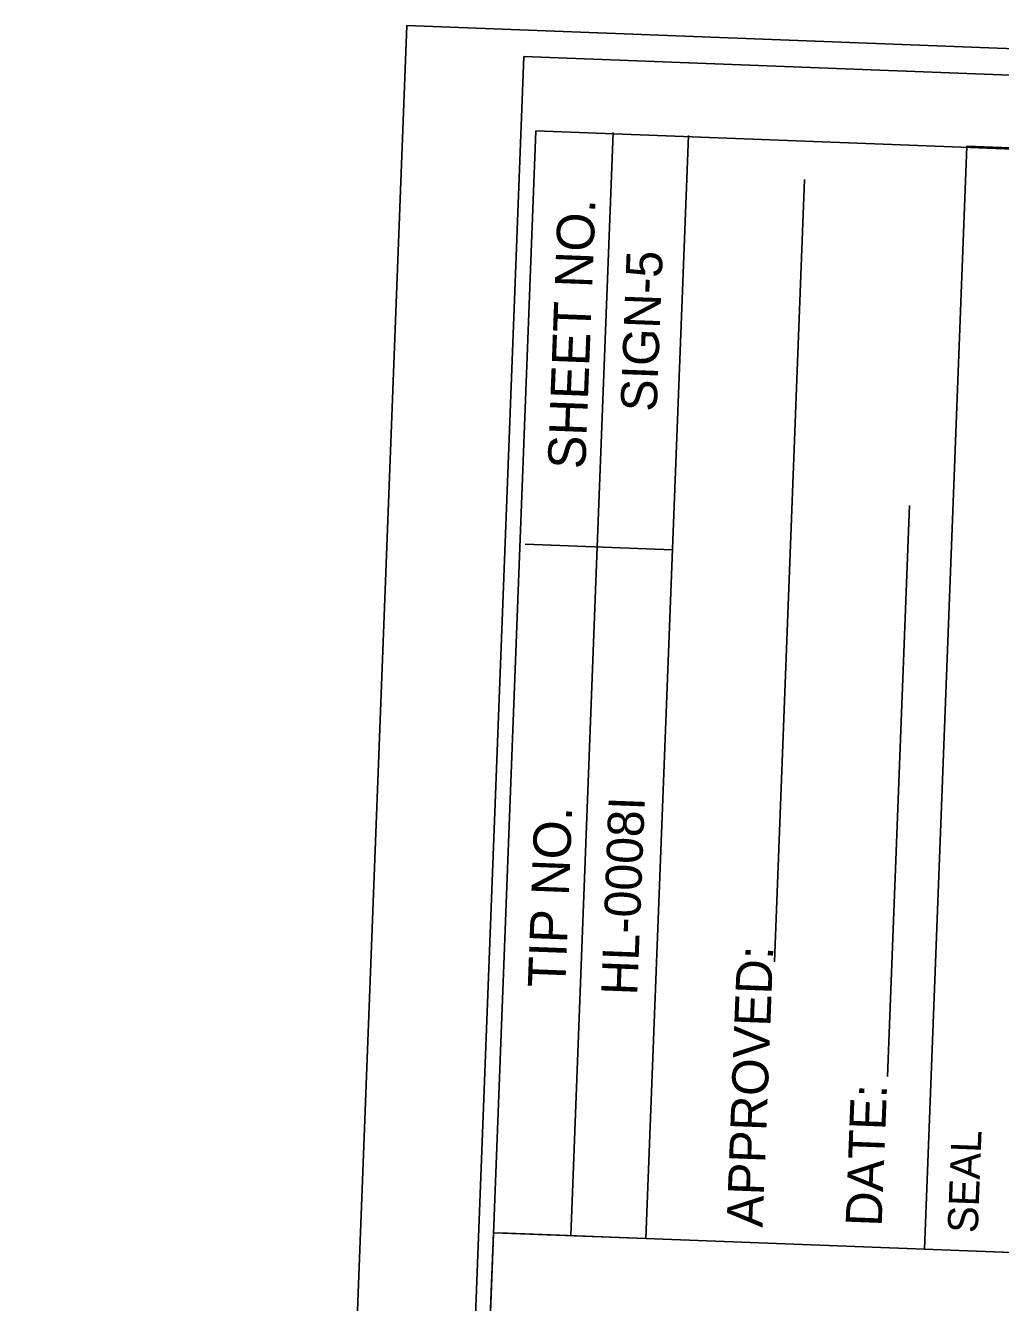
# Model space of a CAD drawing. Extents: x 2093420 to 2100301, y 676254 to 688367.
# Drawn here: x 2097098.7 to 2097263.7, y 687978 to 688194.2 of the extents above; entities that cross this region are included whole.
import ezdxf

# ---------------------------------------------------------------- set-up
doc = ezdxf.new("R2010")
doc.units = 0
for name, color, linetype in [('Default', 7, 'Continuous'), ('Old_Level_10', 7, 'Continuous'), ('Old_Level_2', 7, 'Continuous'), ('Old_Level_4', 7, 'Continuous'), ('Scratch_Level_2', 7, 'Continuous'), ('Sheet Layout Plan Border', 7, 'Continuous'), ('Sheet Plan CELL', 7, 'Continuous'), ('Sheet Plot Border Inside CELL', 7, 'Continuous'), ('Sheet Plot Border Outside CELL', 7, 'Continuous')]:
    doc.layers.add(name, color=color, linetype=linetype)

msp = doc.modelspace()

# ---------------------------------------------------------------- linework, layer by layer
at = {"layer": 'Default'}
for p, q in [((2097195.47, 688105.93), (2097198.17, 688176.1)), ((2097195.47, 688105.93), (2097198.17, 688176.1)), ((2097203.71, 687988.8), (2097210.9, 688175.61)), ((2097203.71, 687988.8), (2097210.9, 688175.61)), ((2097225.44, 688035.68), (2097230.52, 688168.16)), ((2097225.44, 688035.68), (2097230.52, 688168.16)), ((2097244.61, 688016.25), (2097248.32, 688112.94)), ((2097244.61, 688016.25), (2097248.32, 688112.94)), ((2097208.2, 688105.44), (2097183.26, 688106.4)), ((2097208.2, 688105.44), (2097183.26, 688106.4)), ((2097208.2, 688105.44), (2097183.26, 688106.4)), ((2097208.2, 688105.44), (2097183.26, 688106.4)), ((2097190.99, 687989.29), (2097195.47, 688105.93)), ((2097190.99, 687989.29), (2097195.47, 688105.93)), ((2097203.71, 687988.8), (2097177.9, 687989.79)), ((2097203.71, 687988.8), (2097178.79, 687989.75))]:
    msp.add_line(p, q, dxfattribs=at)
at = {"layer": 'Old_Level_2'}
msp.add_line((2097250.84, 687986.99), (2097203.71, 687988.8), dxfattribs=at)
msp.add_line((2097250.84, 687986.99), (2097203.71, 687988.8), dxfattribs=at)
msp.add_lwpolyline([(2097250.84, 687986.99), (2097258.01, 688173.8), (2097369.31, 688169.53), (2097362.14, 687982.72)], close=True, dxfattribs=at)
msp.add_lwpolyline([(2097250.84, 687986.99), (2097258.01, 688173.8), (2097369.31, 688169.53), (2097362.14, 687982.72)], close=True, dxfattribs=at)
at = {"layer": 'Scratch_Level_2'}
msp.add_lwpolyline([(2098179.19, 686705.44), (2097129.59, 686735.95), (2097169.5, 687776.57), (2097177.9, 687989.79), (2097203.71, 687988.8), (2097408.56, 687980.94), (2097412.42, 688081.55), (2098157.98, 688052.95), (2098148.3, 687800.71), (2098221.09, 687797.91)], close=True, dxfattribs=at)
at = {"layer": 'Sheet Layout Plan Border'}
msp.add_lwpolyline([(2098179.19, 686705.44), (2097129.59, 686735.95), (2097169.5, 687776.57), (2097177.9, 687989.79), (2097203.71, 687988.8), (2097408.56, 687980.94), (2097412.42, 688081.55), (2098157.98, 688052.95), (2098148.3, 687800.71), (2098221.09, 687797.91)], close=True, dxfattribs=at)
at = {"layer": 'Sheet Plan CELL'}
msp.add_lwpolyline([(2097185.06, 688176.42), (2097127.55, 686677.48), (2098176.77, 686637.22), (2098234.29, 688136.13)], close=True, dxfattribs=at)
msp.add_lwpolyline([(2097185.06, 688176.42), (2097127.55, 686677.48), (2098176.77, 686637.22), (2098234.29, 688136.13)], close=True, dxfattribs=at)
at = {"layer": 'Sheet Plot Border Inside CELL'}
msp.add_lwpolyline([(2098173.4, 686483.75), (2098237.27, 688148.52), (2097183.06, 688188.98), (2097119.17, 686524.21)], close=True, dxfattribs=at)
msp.add_lwpolyline([(2098173.4, 686483.75), (2098237.27, 688148.52), (2097183.06, 688188.98), (2097119.17, 686524.21)], close=True, dxfattribs=at)
at = {"layer": 'Sheet Plot Border Outside CELL'}
msp.add_lwpolyline([(2098192.89, 686470), (2098257.44, 688152.26), (2097163.24, 688194.24), (2097098.69, 686511.98)], close=True, dxfattribs=at)
msp.add_lwpolyline([(2098192.89, 686470), (2098257.44, 688152.26), (2097163.24, 688194.24), (2097098.69, 686511.98)], close=True, dxfattribs=at)

# ---------------------------------------------------------------- texts
at = {"layer": 'Default'}
for s, height, p in [('SHEET NO.', 6.356, (2097193.43, 688119.04)), ('SHEET NO.', 6.356, (2097193.43, 688119.04)), ('SIGN-5', 6.108, (2097205.51, 688128.78)), ('TIP NO.', 6.356, (2097190.05, 688031.21)), ('TIP NO.', 6.356, (2097190.05, 688031.21)), ('HL-0008I', 6.108, (2097202.23, 688029.93))]:
    msp.add_text(s, height=height, rotation=87.7975, dxfattribs=at).set_placement(p)
at = {"layer": 'Old_Level_10'}
msp.add_text('SEAL', height=5.093, rotation=87.7975, dxfattribs=at).set_placement((2097259.86, 687989.67))
msp.add_text('SEAL', height=5.093, rotation=87.7975, dxfattribs=at).set_placement((2097259.86, 687989.67))
at = {"layer": 'Old_Level_4'}
for s, p in [('APPROVED:', (2097223.45, 687990.63)), ('APPROVED:', (2097223.45, 687990.63)), ('DATE:', (2097243.6, 687990.77)), ('DATE:', (2097243.6, 687990.77))]:
    msp.add_text(s, height=6.108, rotation=87.7975, dxfattribs=at).set_placement(p)

doc.saveas('drawing.dxf')
